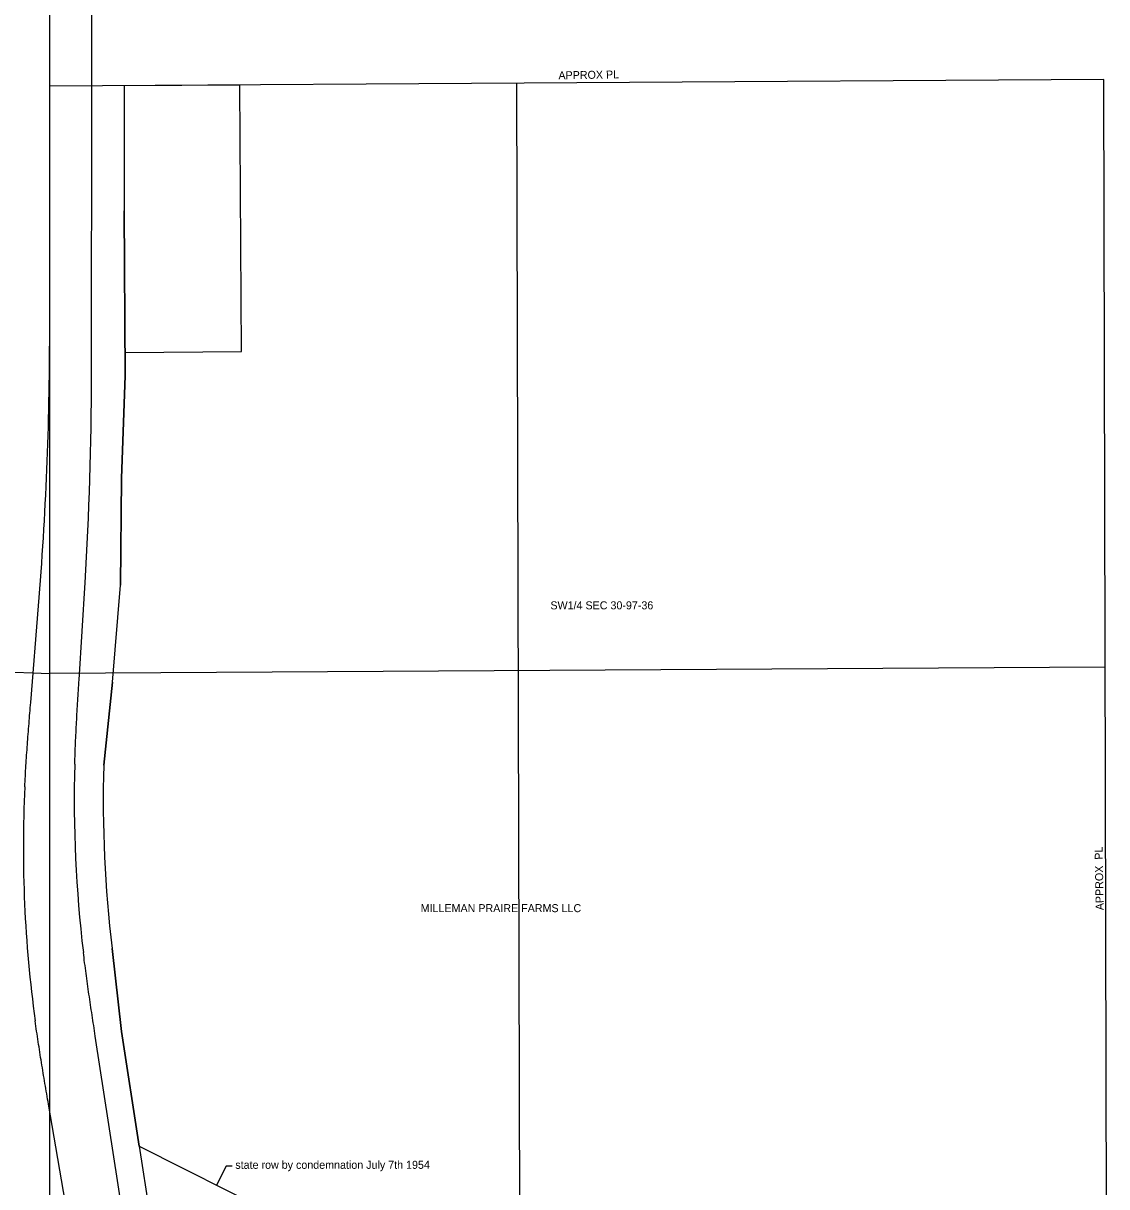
# Model space of a CAD drawing. Extents: x 11521219 to 11528920, y 9587418 to 9599499.
# Drawn here: x 11526483 to 11528920, y 9594212 to 9596829 of the extents above; entities that cross this region are included whole.
import ezdxf

# ---------------------------------------------------------------- set-up
doc = ezdxf.new("R2010")
doc.units = 0
for name, color, linetype in [('Alignment', 7, 'Continuous'), ('DisROW Existing', 7, 'Continuous'), ('DisROW Property Lines', 7, 'Continuous'), ('DisROW Survey', 7, 'Continuous'), ('Section Lines', 7, 'Continuous'), ('Text', 7, 'Continuous')]:
    doc.layers.add(name, color=color, linetype=linetype)

msp = doc.modelspace()

# ---------------------------------------------------------------- linework, layer by layer
at = {"layer": 'Alignment'}
for p, q in [((11526542.9, 9596688), (11526544.3, 9599499.3)), ((11526636.9, 9596688.1), (11526637.9, 9599161)), ((11526542.5, 9596132.7), (11526542.9, 9596688)), ((11526636.5, 9596036.6), (11526636.9, 9596688.1)), ((11526608.5, 9595352.3), (11526622, 9595570.9)), ((11526499.8, 9595301.3), (11526517.5, 9595518.6)), ((11527252.3, 9590607.6), (11526645, 9594551)), ((11527165.7, 9590741), (11526539.8, 9594397.6))]:
    msp.add_line(p, q, dxfattribs=at)
for centre, radius, start, end in [((11518903.1, 9596137.1), 7639.4, 355.35561, 359.9666), ((11518997, 9596041.3), 7639.4, 356.46953, 359.96476), ((11529462.5, 9595081), 2864.8, 178.3695, 186.8543), ((11529348, 9594974.7), 2864.8, 177.2556, 187.8133)]:
    msp.add_arc(centre, radius, start, end, dxfattribs=at)
for points in [[(11526598.9, 9595162.5), (11526599.3, 9595178.3), (11526600.5, 9595210), (11526602.9, 9595257.4), (11526605.5, 9595304.8), (11526607.5, 9595336.4), (11526608.5, 9595352.3)], [(11526486.5, 9595111.8), (11526487.3, 9595127.6), (11526489, 9595159.3), (11526492.3, 9595206.6), (11526495.9, 9595254), (11526498.5, 9595285.6), (11526499.8, 9595301.3)], [(11526645, 9594551), (11526642.6, 9594566.7), (11526637.8, 9594598), (11526630.8, 9594644.9), (11526624.1, 9594692), (11526620.1, 9594723.4), (11526618.2, 9594739.1)], [(11526539.8, 9594397.6), (11526537.1, 9594413.2), (11526531.8, 9594444.4), (11526524, 9594491.3), (11526516.5, 9594538.2), (11526512, 9594569.5), (11526509.8, 9594585.2)]]:
    msp.add_open_spline(points, degree=3, dxfattribs=at)
at = {"layer": 'DisROW Existing'}
for p, q in [((11526709.8, 9596688.8), (11526709.6, 9596407.5)), ((11526712.4, 9596036.9), (11526709.6, 9596407.5)), ((11526703.9, 9595805.3), (11526712.4, 9596036.9)), ((11526702, 9595565.6), (11526703.9, 9595805.3)), ((11526683.5, 9595347.4), (11526702, 9595565.6)), ((11526664, 9595160.3), (11526683.5, 9595347.4)), ((11526704, 9594561.3), (11526682.8, 9594748)), ((11526743.9, 9594303.4), (11526704, 9594561.3)), ((11526743.9, 9594303.4), (11527140.1, 9594104))]:
    msp.add_line(p, q, dxfattribs=at)
msp.add_arc((11529462.7, 9595081.3), 2799.8, 178.3835, 186.8381, dxfattribs=at)
at = {"layer": 'DisROW Property Lines'}
for p, q in [((11528913, 9596702.5), (11526542.9, 9596688)), ((11526709.8, 9596689), (11526709.6, 9596407.5)), ((11526709.8, 9596689), (11526969.8, 9596690.6)), ((11526973.8, 9596090.6), (11526969.8, 9596690.6)), ((11528919.9, 9594058.4), (11528913, 9596702.5)), ((11526709.6, 9596407.5), (11526712.4, 9596036.9)), ((11526712, 9596089), (11526973.8, 9596090.6)), ((11526712.4, 9596036.9), (11526703.9, 9595805.3)), ((11526703.9, 9595805.3), (11526702, 9595565.6)), ((11526683.5, 9595347.4), (11526702, 9595565.6)), ((11526683.5, 9595347.4), (11526664, 9595160.3)), ((11526682.8, 9594748), (11526704, 9594561.3)), ((11526704, 9594561.3), (11526743.9, 9594303.4)), ((11526743.9, 9594303.4), (11526783.4, 9594047.1))]:
    msp.add_line(p, q, dxfattribs=at)
msp.add_arc((11529462.7, 9595081.3), 2799.8, 178.3835, 186.8381, dxfattribs=at)
at = {"layer": 'DisROW Survey'}
for p, q in [((11526939.2, 9594258.3), (11526917.9, 9594215.8)), ((11526952.9, 9594258.3), (11526939.2, 9594258.3))]:
    msp.add_line(p, q, dxfattribs=at)
at = {"layer": 'Section Lines'}
for p, q in [((11526542.5, 9594045.8), (11526542.9, 9596688)), ((11527599.9, 9594051.4), (11527593, 9596694.4)), ((11523865.2, 9595465.5), (11526542.7, 9595366.9)), ((11528916.4, 9595380.5), (11526542.7, 9595366.9))]:
    msp.add_line(p, q, dxfattribs=at)

# ---------------------------------------------------------------- texts
at = {"layer": 'Text'}
for s, rotation, p in [('APPROX PL', 1, (11527686.8, 9596703)), ('APPROX  PL', 91, (11528913.1, 9594834.2))]:
    msp.add_text(s, height=18, rotation=rotation, dxfattribs=at).set_placement(p)
for s, p in [('SW1/4 SEC 30-97-36', (11527668.6, 9595510.9)), ('MILLEMAN PRAIRE FARMS LLC', (11527376.8, 9594829.7)), ('state row by condemnation July 7th 1954', (11526960, 9594252.3))]:
    msp.add_text(s, height=18, dxfattribs=at).set_placement(p)

doc.saveas('drawing.dxf')
